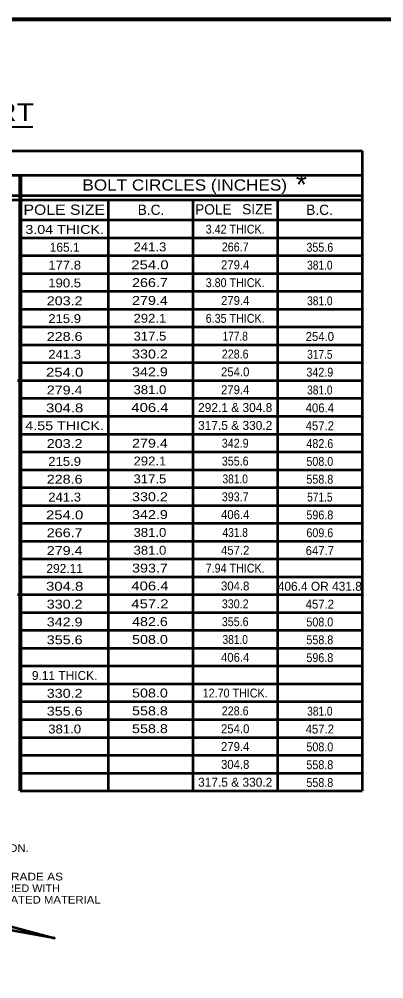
# Model space of a CAD drawing. Extents: x -711 to 145, y 25 to 569.
# Drawn here: x -366 to -252.6, y 264.5 to 562.7 of the extents above; entities that cross this region are included whole.
import ezdxf
from ezdxf.enums import TextEntityAlignment as Align

# ---------------------------------------------------------------- set-up
doc = ezdxf.new("R2010")
doc.units = 0
doc.header["$LTSCALE"] = 1.1
doc.layers.add('1', color=7, linetype='Continuous', lineweight=53)

msp = doc.modelspace()

# ---------------------------------------------------------------- linework, layer by layer
at = {"layer": '1', "lineweight": 40}
msp.add_line((-502.259, 529.228), (-361.778, 529.228), dxfattribs=at)
at = {"layer": '1'}
for p, q in [((-612.309, 521.791), (-259.32, 521.791)), ((-259.32, 521.791), (-259.32, 504.113)), ((-612.309, 514.168), (-259.32, 514.168)), ((-612.309, 507.931), (-259.32, 507.931)), ((-612.309, 506.545), (-259.32, 506.545)), ((-338.322, 506.545), (-338.322, 322.9)), ((-311.988, 506.545), (-311.988, 322.9)), ((-285.654, 506.545), (-285.654, 322.9)), ((-365.755, 500.308), (-259.32, 500.308)), ((-365.755, 494.764), (-259.32, 494.764)), ((-365.755, 489.22), (-259.32, 489.22)), ((-365.755, 483.676), (-259.32, 483.676)), ((-365.548, 478.132), (-259.32, 478.132)), ((-365.548, 472.588), (-259.32, 472.588)), ((-365.548, 467.044), (-259.32, 467.044)), ((-365.755, 461.5), (-259.32, 461.5)), ((-365.755, 455.956), (-259.32, 455.956)), ((-366.535, 450.412), (-259.32, 450.412)), ((-365.755, 444.868), (-259.32, 444.868)), ((-365.755, 439.324), (-259.32, 439.324)), ((-366.041, 433.78), (-259.32, 433.78)), ((-365.548, 428.236), (-259.32, 428.236)), ((-365.548, 422.692), (-259.32, 422.692)), ((-365.548, 417.148), (-259.32, 417.148)), ((-365.548, 411.604), (-259.32, 411.604)), ((-365.548, 406.06), (-259.32, 406.06)), ((-365.548, 400.516), (-259.32, 400.516)), ((-365.755, 394.972), (-259.32, 394.972)), ((-365.755, 389.428), (-259.32, 389.428)), ((-366.535, 383.884), (-259.32, 383.884)), ((-365.755, 378.34), (-259.32, 378.34)), ((-365.755, 372.796), (-259.32, 372.796)), ((-365.755, 367.252), (-259.32, 367.252)), ((-365.755, 361.708), (-259.32, 361.708)), ((-365.755, 356.164), (-259.32, 356.164)), ((-365.755, 350.62), (-259.32, 350.62)), ((-365.755, 345.076), (-259.32, 345.076)), ((-365.755, 339.532), (-259.32, 339.532)), ((-365.755, 333.988), (-259.32, 333.988)), ((-365.755, 328.444), (-259.32, 328.444)), ((-365.755, 322.9), (-259.32, 322.9))]:
    msp.add_line(p, q, dxfattribs=at)
at = {"layer": '1', "lineweight": 80}
msp.add_line((-365.755, 514.168), (-365.755, 322.9), dxfattribs=at)
at = {"layer": '1', "lineweight": 35}
msp.add_line((-364.238, 278.752), (-363.59, 279.399), dxfattribs=at)
at = {"layer": '1', "lineweight": 158}
msp.add_lwpolyline([(138.105, 562.675), (-653.595, 562.575), (-653.495, 36.575)], dxfattribs=at)
at = {"layer": '1'}
for points in [[(-259.32, 506.545), (-259.32, 356.164), (-259.32, 322.9)], [(-412.994, 292.637), (-355.039, 277.108), (-441.956, 292.637)]]:
    msp.add_lwpolyline(points, dxfattribs=at)

# ---------------------------------------------------------------- texts
for s, height, width, p in [('ANCHOR BOLTS & BOLT CHART', 5.544, 1.2, (-498.833, 531.024)), ('BOLT CIRCLES (INCHES)', 3.465, 1.15, (-346.366, 509.433)), ('POLE SIZE', 3.188, 1.15, (-364.682, 501.884)), ('CONC. POLE FDN.', 2.4, 1.1, (-394.047, 303.898)), ('SITE GRADE AS', 2.4, 1.15, (-380.7, 295.057)), ('REQUIRED WITH', 2.4, 1.05, (-380.7, 291.457)), ('EXCAVATED MATERIAL', 2.4, 1.1, (-380.7, 287.857))]:
    msp.add_text(s, height=height, dxfattribs=dict(at, width=width)).set_placement(p)
for s, height, p in [('*', 6.653, (-279.971, 507.97)), ('B.C.', 3.188, (-329.155, 501.852)), ('POLE', 3.188, (-311.294, 501.982)), ('SIZE', 3.188, (-296.668, 502.046)), ('B.C.', 3.188, (-276.737, 501.852))]:
    msp.add_text(s, height=height, dxfattribs=at).set_placement(p)
for s, width, p in [('3.04 THICK.', 1.2, (-351.89, 495.961)), ('3.42 THICK.', 0.9, (-298.829, 496.055)), ('241.3', 1.1, (-325.358, 490.526)), ('266.7', 0.9, (-298.829, 490.511)), ('355.6', 0.9, (-272.499, 490.414)), ('177.8', 1.1, (-351.89, 484.873)), ('254.0', 1.25, (-325.358, 484.982)), ('279.4', 0.95, (-298.829, 484.967)), ('381.0', 0.85, (-272.499, 484.87)), ('190.5', 1.1, (-351.89, 479.329)), ('266.7', 1.2, (-325.358, 479.438)), ('3.80 THICK.', 0.9, (-298.829, 479.423)), ('203.2', 1.2, (-351.89, 473.785)), ('279.4', 1.2, (-325.358, 473.894)), ('279.4', 0.95, (-298.829, 473.879)), ('381.0', 0.85, (-272.499, 473.782)), ('292.1', 1.1, (-325.358, 468.35)), ('6.35 THICK.', 0.9, (-298.829, 468.335)), ('215.9', 1.1, (-351.89, 468.241)), ('228.6', 1.2, (-351.89, 462.697)), ('317.5', 1.1, (-325.358, 462.806)), ('177.8', 0.85, (-298.829, 462.791)), ('254.0', 0.95, (-272.499, 462.694)), ('241.3', 1.1, (-351.89, 457.153)), ('330.2', 1.2, (-325.358, 457.262)), ('228.6', 0.9, (-298.829, 457.247)), ('317.5', 0.85, (-272.499, 457.15)), ('254.0', 1.25, (-351.89, 451.609)), ('342.9', 1.2, (-325.358, 451.718)), ('254.0', 0.95, (-298.829, 451.703)), ('342.9', 0.9, (-272.499, 451.606)), ('279.4', 1.2, (-351.89, 446.065)), ('381.0', 1.1, (-325.358, 446.174)), ('279.4', 0.95, (-298.829, 446.159)), ('381.0', 0.85, (-272.499, 446.062)), ('304.8', 1.25, (-351.89, 440.521)), ('406.4', 1.25, (-325.358, 440.63)), ('406.4', 0.95, (-272.499, 440.518)), ('4.55 THICK.', 1.2, (-351.89, 434.977)), ('457.2', 0.95, (-272.499, 434.974)), ('279.4', 1.2, (-325.358, 429.542)), ('203.2', 1.2, (-351.89, 429.433)), ('342.9', 0.9, (-298.829, 429.527)), ('482.6', 0.9, (-272.499, 429.43)), ('215.9', 1.1, (-351.89, 423.889)), ('292.1', 1.1, (-325.358, 423.998)), ('355.6', 0.9, (-298.829, 423.983)), ('508.0', 0.9, (-272.499, 423.886)), ('228.6', 1.2, (-351.89, 418.345)), ('317.5', 1.1, (-325.358, 418.454)), ('381.0', 0.85, (-298.829, 418.439)), ('558.8', 0.9, (-272.499, 418.342)), ('241.3', 1.1, (-351.89, 412.801)), ('330.2', 1.2, (-325.358, 412.91)), ('393.7', 0.9, (-298.829, 412.895)), ('571.5', 0.85, (-272.499, 412.798)), ('254.0', 1.25, (-351.89, 407.257)), ('342.9', 1.2, (-325.358, 407.366)), ('406.4', 0.95, (-298.829, 407.351)), ('596.8', 0.9, (-272.499, 407.254)), ('266.7', 1.2, (-351.89, 401.713)), ('381.0', 1.1, (-325.358, 401.822)), ('431.8', 0.85, (-298.829, 401.807)), ('609.6', 0.9, (-272.499, 401.71)), ('279.4', 1.2, (-351.89, 396.169)), ('381.0', 1.1, (-325.358, 396.278)), ('457.2', 0.95, (-298.829, 396.263)), ('647.7', 0.95, (-272.499, 396.166)), ('393.7', 1.2, (-325.358, 390.734)), ('7.94 THICK.', 0.9, (-298.829, 390.719)), ('304.8', 1.25, (-351.89, 385.081)), ('406.4', 1.25, (-325.358, 385.19)), ('304.8', 0.95, (-298.829, 385.175)), ('330.2', 1.2, (-351.89, 379.537)), ('457.2', 1.25, (-325.358, 379.646)), ('330.2', 0.9, (-298.829, 379.631)), ('457.2', 0.95, (-272.499, 379.534)), ('342.9', 1.2, (-351.89, 373.993)), ('482.6', 1.2, (-325.358, 374.102)), ('355.6', 0.9, (-298.829, 374.087)), ('508.0', 0.9, (-272.499, 373.99)), ('355.6', 1.2, (-351.89, 368.449)), ('508.0', 1.2, (-325.358, 368.558)), ('381.0', 0.85, (-298.829, 368.543)), ('558.8', 0.9, (-272.499, 368.446)), ('406.4', 0.95, (-298.829, 362.999)), ('596.8', 0.9, (-272.499, 362.902)), ('330.2', 1.2, (-351.89, 351.817)), ('508.0', 1.2, (-325.358, 351.926)), ('12.70 THICK.', 0.9, (-298.829, 351.911)), ('355.6', 1.2, (-351.89, 346.273)), ('558.8', 1.2, (-325.358, 346.382)), ('228.6', 0.9, (-298.829, 346.367)), ('381.0', 0.85, (-272.499, 346.27)), ('381.0', 1.1, (-351.89, 340.729)), ('558.8', 1.2, (-325.358, 340.838)), ('254.0', 0.95, (-298.829, 340.823)), ('457.2', 0.95, (-272.499, 340.726)), ('279.4', 0.95, (-298.829, 335.279)), ('508.0', 0.9, (-272.499, 335.182)), ('304.8', 0.95, (-298.829, 329.735)), ('558.8', 0.9, (-272.499, 329.638)), ('558.8', 0.9, (-272.499, 324.094))]:
    msp.add_text(s, height=2.772, dxfattribs=dict(at, width=width)).set_placement(p, align=Align.CENTER)
for s, p in [('165.1', (-351.89, 490.417)), ('292.1 & 304.8', (-298.829, 440.615)), ('317.5 & 330.2', (-298.829, 435.071)), ('292.11', (-351.89, 390.625)), ('406.4 OR 431.8', (-272.499, 385.078)), ('9.11 THICK.', (-351.89, 357.361)), ('317.5 & 330.2', (-298.829, 324.191))]:
    msp.add_text(s, height=2.772, dxfattribs=at).set_placement(p, align=Align.CENTER)

doc.saveas('drawing.dxf')
